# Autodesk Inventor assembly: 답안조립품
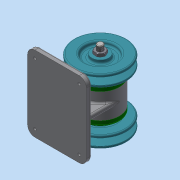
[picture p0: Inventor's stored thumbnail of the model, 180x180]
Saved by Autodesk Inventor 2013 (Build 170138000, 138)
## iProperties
Created: 2019-09
Part Number: 답안조립품
Document SubType Name: Assembly
Designer: Administrator
Author: Administrator
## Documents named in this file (10)
- C:\Users\Administrator\Desktop\490904V1050\답안조립품.iam
- C:\Users\Administrator\Desktop\490904V1050\본체.ipt
- C:\Users\Administrator\Desktop\490904V1050\V-벨트풀리.ipt
- C:\Users\Administrator\Desktop\490904V1050\너트 M10x1.ipt
- C:\Users\Administrator\Desktop\490904V1050\베어링 6004.ipt
- C:\Users\Administrator\Desktop\490904V1050\볼트 M4.ipt
- C:\Users\Administrator\Desktop\490904V1050\오일 실 17 30 5.ipt
- C:\Users\Administrator\Desktop\490904V1050\축.ipt
- C:\Users\Administrator\Desktop\490904V1050\커버.ipt
- C:\Users\Administrator\Desktop\490904V1050\키 5 x 5 x 12.ipt
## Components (2 placed, 1 different names)
1. V-벨트풀리:1 — 각도:2
2. V-벨트풀리:2 — 각도:3
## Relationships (2: Angle 2)
- 각도:2 [Angle]: V-벨트풀리:1
- 각도:3 [Angle]: V-벨트풀리:2
